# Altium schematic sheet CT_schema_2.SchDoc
size 276 x 169 mm
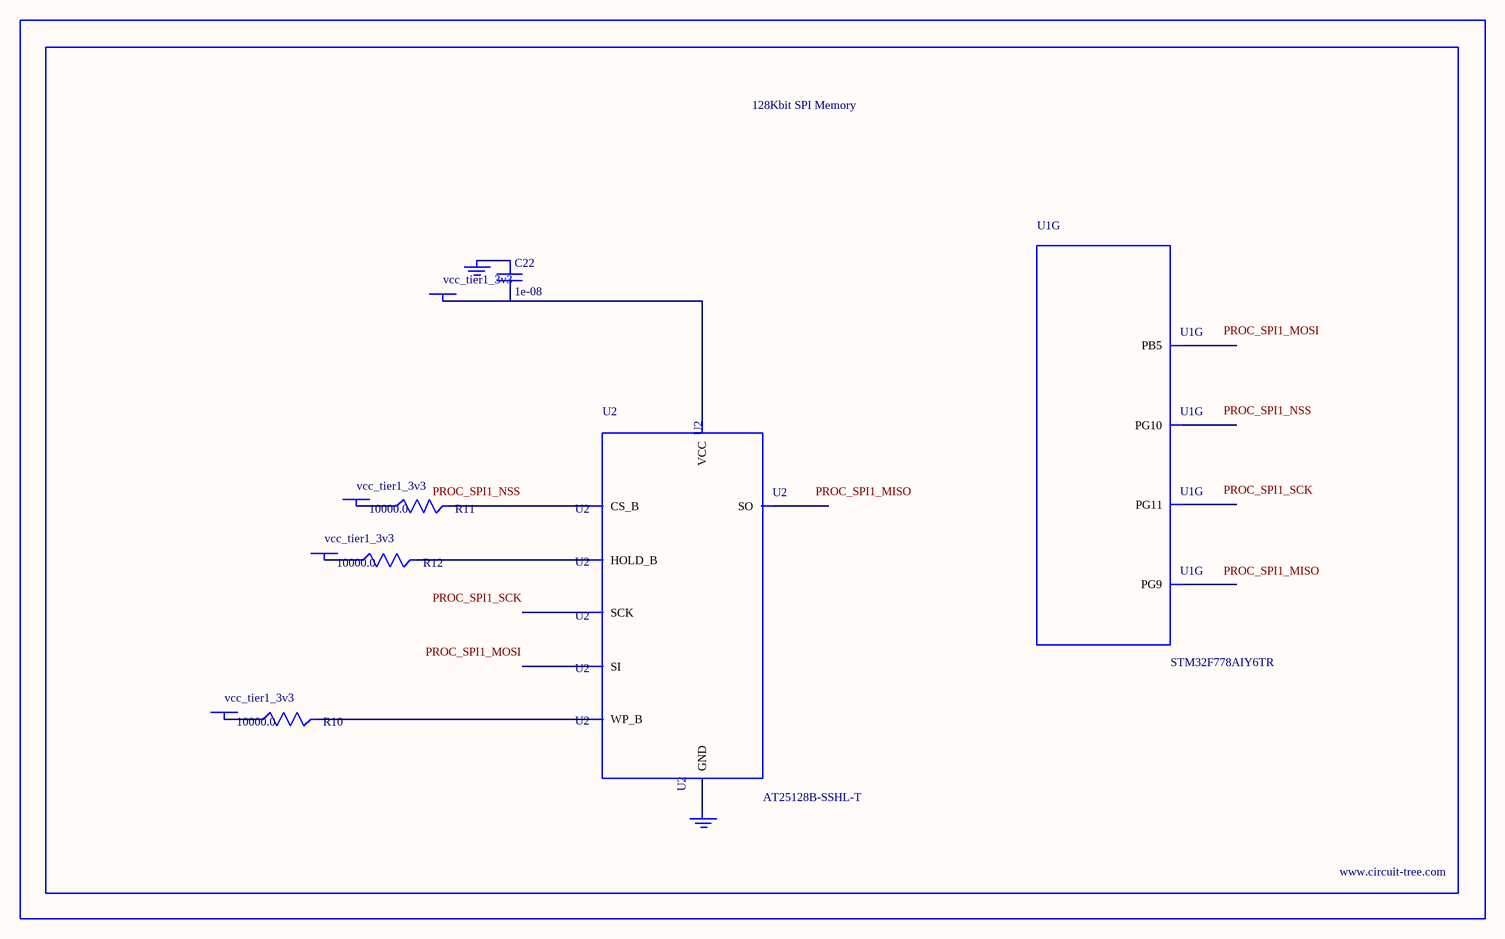
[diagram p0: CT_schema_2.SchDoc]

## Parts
BORDER1  (no value)
C22  1e-08  [C0402]
GND_INSTANCE_1_0  (no value)
GND_INSTANCE_1_1  (no value)
POWER_INSTANCE_1_0  vcc_tier1_3v3
POWER_INSTANCE_1_1  vcc_tier1_3v3
POWER_INSTANCE_1_2  vcc_tier1_3v3
POWER_INSTANCE_1_3  vcc_tier1_3v3
R10  10000.0  [R0603]
R11  10000.0  [R0603]
R12  10000.0  [R0603]
U1  STM32F778AIY6TR  [WLCSP180]  (part G of 15)
U2  AT25128B-SSHL-T  [SOIC-8]

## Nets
NetC22_1: C22.1 GND_INSTANCE_1_0.0(GND)
NetC22_2: C22.2 POWER_INSTANCE_1_3.0(PWR) U2.8(VCC)
NetGND_INSTANCE_1_1_0: GND_INSTANCE_1_1.0(GND) U2.4(GND)
NetPOWER_INSTANCE_1_0_0: POWER_INSTANCE_1_0.0(PWR) R11.1
NetPOWER_INSTANCE_1_1_0: POWER_INSTANCE_1_1.0(PWR) R10.1
NetPOWER_INSTANCE_1_2_0: POWER_INSTANCE_1_2.0(PWR) R12.1
NetR10_2: R10.2 U2.3(WP_B)
NetR11_2: R11.2 U2.1(CS_B)
NetR12_2: R12.2 U2.7(HOLD_B)

Not connected (* = marked no-connect by the designer): U1 A7(PG10) A9(PB5) B7(PG11) C6(PG9); U2 2(SO) 5(SI) 6(SCK)

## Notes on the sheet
- Labels drawn without touching a wire or pin: PROC_SPI1_MISO, PROC_SPI1_MOSI, PROC_SPI1_NSS, PROC_SPI1_SCK

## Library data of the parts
BORDER1 = BORDER_PAGE1
C22 = C0402C103K3RAC
GND_INSTANCE_1_0 GND_INSTANCE_1_1 = GND
POWER_INSTANCE_1_0-POWER_INSTANCE_1_3 = PWR
R10-R12 = RC0603JR-0710KL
